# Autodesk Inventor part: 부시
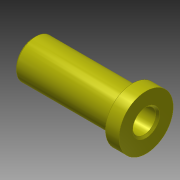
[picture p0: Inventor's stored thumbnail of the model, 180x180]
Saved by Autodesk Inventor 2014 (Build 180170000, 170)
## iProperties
Created: 2016-11
Part Number: 부시
Material: 강철, 연강
Document SubType Name: Modeling
Designer: mduedu
Density: 1 g/cm^3
Appearance: 노란색
Author: mduedu
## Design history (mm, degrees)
sketch "스케치1"
  geometry: L1 (0, 0)-(58, 0); L2 (58, 0)-(58, 14); L3 (58, 14)-(51, 14); L4 (51, 14)-(51, 10); L5 (51, 10)-(0, 10); L6 (0, 10)-(0, 0)
  constraints: 12 end point, 3 parallel, 2 perpendicular, 1 horizontal
  dimensions: "d0" = 58 distance of L1.start L1.end; "d1" = 7 distance of L2.end L3.end; "d2" = 28 diameter of L3 L1; "d3" = 20 diameter of L5 L1
revolve "회전1" sketch "스케치1" stored, may be unused: angle "d4" = 90 deg
hole "구멍1" diameter "d7" = 12; stored, may be unused: countersink angle "d11" = 90 deg, drill point angle "d13" = 118 deg; dims "d5" = 10, "d6" = 10, "d8" = 6, "d9" = 4, "d10" = 2, "d12" = 8
chamfer "모따기1" distance "d14" = 1; stored, may be unused: second distance "d15" = 2, angle "d16" = 45 deg
node "솔리드1"
